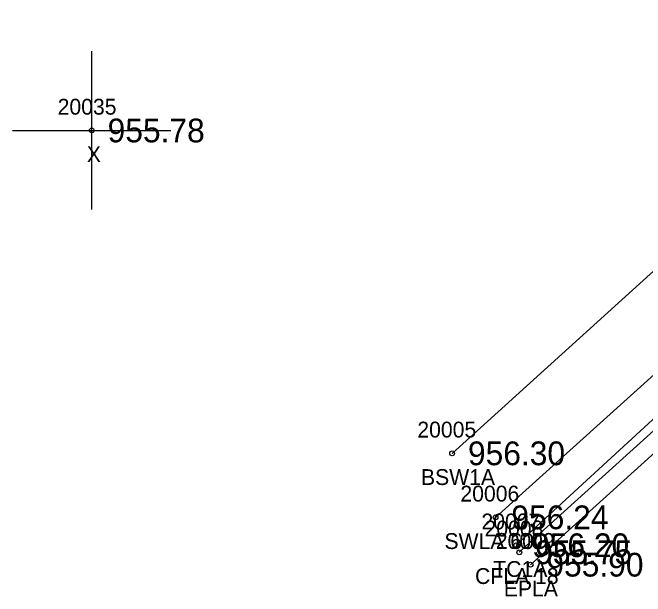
# Model space of a CAD drawing. Extents: x 1576181 to 1577685, y 1099396 to 1101490.
# Drawn here: x 1576313.01 to 1576352.99, y 1099564.97 to 1099601.85 of the extents above; entities that cross this region are included whole.
import ezdxf

# ---------------------------------------------------------------- set-up
doc = ezdxf.new("R2010")
doc.units = 0
for name, color, linetype in [('RD_DTM_BkLn2', 7, 'Continuous'), ('RD_EX_Conc', 7, 'Continuous'), ('RD_EX_Conc_txCode', 7, 'Continuous'), ('RD_EX_Misc', 7, 'Continuous'), ('RD_EX_Misc_txCode', 7, 'Continuous'), ('RD_EX_Road', 7, 'Continuous'), ('RD_EX_Road_txCode', 7, 'Continuous'), ('RD_EX_TX_Conc_ELEV', 7, 'Continuous'), ('RD_EX_TX_Misc_ELEV', 7, 'Continuous'), ('RD_EX_TX_Road_ELEV', 7, 'Continuous'), ('RD_SMD_Locator', 7, 'Continuous')]:
    doc.layers.add(name, color=color, linetype=linetype)

msp = doc.modelspace()

# ---------------------------------------------------------------- linework, layer by layer
at = {"layer": 'RD_DTM_BkLn2'}
msp.add_line((1576344.828, 1099568.202), (1576365.195, 1099586.953), dxfattribs=at)
at = {"layer": 'RD_EX_Conc'}
for p, q in [((1576345.022, 1099567.755), (1576372.484, 1099592.673)), ((1576340.778, 1099574.008), (1576360.313, 1099591.697))]:
    msp.add_line(p, q, dxfattribs=at)
msp.add_lwpolyline([(1576343.522, 1099569.964), (1576363.781, 1099588.213), (1576365.195, 1099586.953), (1576376.121, 1099596.515), (1576380.795, 1099600.714), (1576379.736, 1099601.846)], dxfattribs=at)
at = {"layer": 'RD_EX_Misc'}
for p, q in [((1576318.013, 1099589.403), (1576318.013, 1099599.403)), ((1576313.013, 1099594.403), (1576323.013, 1099594.403))]:
    msp.add_line(p, q, dxfattribs=at)
at = {"layer": 'RD_EX_Road'}
msp.add_lwpolyline([(1576345.735, 1099566.974), (1576373.249, 1099591.824), (1576377.221, 1099595.34), (1576381.818, 1099599.483), (1576383.698, 1099601.102)], dxfattribs=at)
at = {"layer": 'RD_SMD_Locator'}
for centre in [(1576318.013, 1099594.403), (1576340.778, 1099574.008), (1576343.522, 1099569.964), (1576344.828, 1099568.202), (1576345.022, 1099567.755), (1576345.735, 1099566.974)]:
    msp.add_circle(centre, 0.15, dxfattribs=at)

# ---------------------------------------------------------------- texts
at = {"layer": 'RD_EX_Conc_txCode'}
for s, p in [('20005', (1576338.581, 1099575.008)), ('BSW1A', (1576338.809, 1099572.008)), ('20006', (1576341.301, 1099570.964)), ('20007', (1576342.631, 1099569.202)), ('20008', (1576342.825, 1099568.755)), ('SWLA 60', (1576340.293, 1099567.964)), ('TC1A', (1576343.379, 1099566.202)), ('CFLA 18', (1576342.227, 1099565.755))]:
    msp.add_text(s, height=1, dxfattribs=at).set_placement(p)
at = {"layer": 'RD_EX_Misc_txCode'}
for s, p in [('20035', (1576315.856, 1099595.403)), ('X', (1576317.698, 1099592.403))]:
    msp.add_text(s, height=1, dxfattribs=at).set_placement(p)
at = {"layer": 'RD_EX_Road_txCode'}
for s, p in [('20009', (1576343.538, 1099567.974)), ('EPLA', (1576344.042, 1099564.974))]:
    msp.add_text(s, height=1, dxfattribs=at).set_placement(p)
at = {"layer": 'RD_EX_TX_Conc_ELEV'}
for s, p in [('956.30', (1576341.778, 1099573.258)), ('956.24', (1576344.522, 1099569.214)), ('956.20', (1576345.828, 1099567.452)), ('955.75', (1576346.022, 1099567.005))]:
    msp.add_text(s, height=1.5, dxfattribs=at).set_placement(p)
at = {"layer": 'RD_EX_TX_Misc_ELEV'}
msp.add_text('955.78', height=1.5, dxfattribs=at).set_placement((1576319.013, 1099593.653))
at = {"layer": 'RD_EX_TX_Road_ELEV'}
msp.add_text('955.90', height=1.5, dxfattribs=at).set_placement((1576346.735, 1099566.224))

doc.saveas('drawing.dxf')
